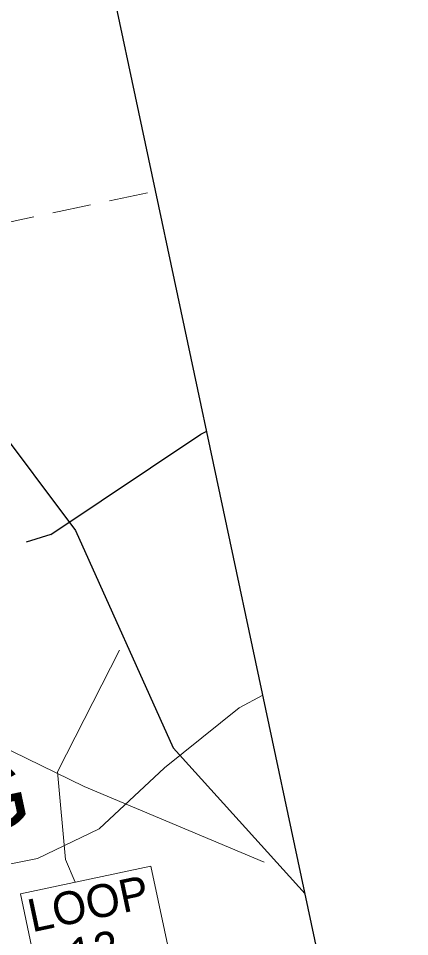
# Model space of a CAD drawing. Extents: x 2357218 to 2371708, y 6973728 to 6980157.
# Drawn here: x 2357681 to 2357741.7, y 6974748.1 to 6974890.5 of the extents above; entities that cross this region are included whole.
import ezdxf

# ---------------------------------------------------------------- set-up
doc = ezdxf.new("R2010")
doc.units = 0
doc.header["$LTSCALE"] = 2
doc.linetypes.add('MEDIUM_DASHED', pattern=[4.5, 3, -1.5])
doc.layers.add('62', color=7, linetype='Continuous', lineweight=13)
doc.layers.add('63', color=7, linetype='Continuous', lineweight=13)

msp = doc.modelspace()

# ---------------------------------------------------------------- linework, layer by layer
at = {"layer": '62', "linetype": 'MEDIUM_DASHED'}
msp.add_line((2357701.055, 6974863.476), (2357262.587, 6974770.278), dxfattribs=at)
at = {"layer": '62', "lineweight": 25}
msp.add_line((2357686.102, 6974810.447), (2357682.239, 6974809.258), dxfattribs=at)
at = {"layer": '62'}
for p, q in [((2357691.251, 6974771.4), (2357671.217, 6974781.127)), ((2357691.251, 6974771.4), (2357719.143, 6974759.66)), ((2357688.351, 6974760.039), (2357689.832, 6974756.536))]:
    msp.add_line(p, q, dxfattribs=at)
at = {"layer": '62', "lineweight": 25}
for points in [[(2357242.867, 6974863.05), (2357339.603, 6974407.945), (2357779.37, 6974501.42), (2357682.634, 6974956.528)], [(2357676.771, 6974828.593), (2357689.879, 6974811.067), (2357705.075, 6974777.351), (2357725.526, 6974754.738)], [(2357686.102, 6974810.447), (2357709.343, 6974826.015), (2357710.27, 6974826.51)]]:
    msp.add_lwpolyline(points, dxfattribs=at)
at = {"layer": '62'}
for points in [[(2357688.351, 6974760.039), (2357687.088, 6974773.668), (2357696.741, 6974792.533)], [(2357595.779, 6974740.777), (2357608.657, 6974744.365), (2357631.126, 6974750.887), (2357652.256, 6974754.413), (2357666.337, 6974756.671), (2357684.011, 6974760.219), (2357693.6, 6974764.79), (2357703.731, 6974774.259), (2357715.298, 6974783.597), (2357718.976, 6974785.553)]]:
    msp.add_lwpolyline(points, dxfattribs=at)
msp.add_lwpolyline([(2357681.358, 6974754.732), (2357684.602, 6974739.482), (2357704.849, 6974743.785), (2357701.607, 6974759.039)], close=True, dxfattribs=at)
at = {"layer": '63', "linetype": 'MEDIUM_DASHED'}
msp.add_line((2357701.055, 6974863.476), (2357262.587, 6974770.278), dxfattribs=at)
at = {"layer": '63', "lineweight": 25}
msp.add_line((2357686.102, 6974810.447), (2357682.239, 6974809.258), dxfattribs=at)
at = {"layer": '63'}
for p, q in [((2357691.251, 6974771.4), (2357671.217, 6974781.127)), ((2357691.251, 6974771.4), (2357719.143, 6974759.66)), ((2357688.351, 6974760.039), (2357689.832, 6974756.536))]:
    msp.add_line(p, q, dxfattribs=at)
at = {"layer": '63', "lineweight": 25}
for points in [[(2357242.867, 6974863.05), (2357339.603, 6974407.945), (2357779.37, 6974501.42), (2357682.634, 6974956.528)], [(2357676.771, 6974828.593), (2357689.879, 6974811.067), (2357705.075, 6974777.351), (2357725.526, 6974754.738)], [(2357686.102, 6974810.447), (2357709.343, 6974826.015), (2357710.27, 6974826.51)]]:
    msp.add_lwpolyline(points, dxfattribs=at)
at = {"layer": '63'}
for points in [[(2357688.351, 6974760.039), (2357687.088, 6974773.668), (2357696.741, 6974792.533)], [(2357595.779, 6974740.777), (2357608.657, 6974744.365), (2357631.126, 6974750.887), (2357652.256, 6974754.413), (2357666.337, 6974756.671), (2357684.011, 6974760.219), (2357693.6, 6974764.79), (2357703.731, 6974774.259), (2357715.298, 6974783.597), (2357718.976, 6974785.553)]]:
    msp.add_lwpolyline(points, dxfattribs=at)
msp.add_lwpolyline([(2357681.358, 6974754.732), (2357684.602, 6974739.482), (2357704.849, 6974743.785), (2357701.607, 6974759.039)], close=True, dxfattribs=at)

# ---------------------------------------------------------------- texts
at = {"layer": '62', "width": 1.1}
msp.add_text('IRVING', height=10.21, rotation=12, dxfattribs=at).set_placement((2357633.011, 6974755.016))
at = {"layer": '62'}
for s, p in [('LOOP', (2357683.16, 6974748.745)), ('12', (2357689.637, 6974742.622))]:
    msp.add_text(s, height=5.099, rotation=12, dxfattribs=at).set_placement(p)
at = {"layer": '63', "width": 1.1}
msp.add_text('IRVING', height=10.21, rotation=12, dxfattribs=at).set_placement((2357633.011, 6974755.016))
at = {"layer": '63'}
for s, p in [('LOOP', (2357683.16, 6974748.745)), ('12', (2357689.637, 6974742.622))]:
    msp.add_text(s, height=5.099, rotation=12, dxfattribs=at).set_placement(p)

doc.saveas('drawing.dxf')
